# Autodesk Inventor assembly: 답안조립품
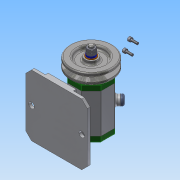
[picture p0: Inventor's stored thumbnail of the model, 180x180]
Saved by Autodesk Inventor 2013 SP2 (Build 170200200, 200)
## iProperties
Created: 2018-06
Part Number: 답안조립품
Document SubType Name: Assembly
Designer: Administrator
Author: Administrator
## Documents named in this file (16)
- C:\Users\Administrator\Desktop\480608V1010\답안조립품.iam
- C:\Users\Administrator\Desktop\480608V1010\V벨트풀리.ipt
- C:\Users\Administrator\Desktop\480608V1010\고무캡.ipt
- C:\Users\Administrator\Desktop\480608V1010\너트 M8.ipt
- 너트 M8.ipt
- C:\Users\Administrator\Desktop\480608V1010\뒤커버.ipt
- C:\Users\Administrator\Desktop\480608V1010\베어링 15x32x9.ipt
- C:\Users\Administrator\Desktop\480608V1010\본체.ipt
- C:\Users\Administrator\Desktop\480608V1010\볼트 M4x12.ipt
- C:\Users\Administrator\Desktop\480608V1010\스프링와셔 8.ipt
- C:\Users\Administrator\Desktop\480608V1010\앞커버.ipt
- C:\Users\Administrator\Desktop\480608V1010\오일 실 15 25 7.ipt
- C:\Users\Administrator\Desktop\480608V1010\와셔 8x17.ipt
- C:\Users\Administrator\Desktop\480608V1010\축.ipt
- C:\Users\Administrator\Desktop\480608V1010\키 3x3x12.ipt
- 키 3x3x12.ipt
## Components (2 placed, 2 different names)
1. V벨트풀리:1
2. 고무캡:1
